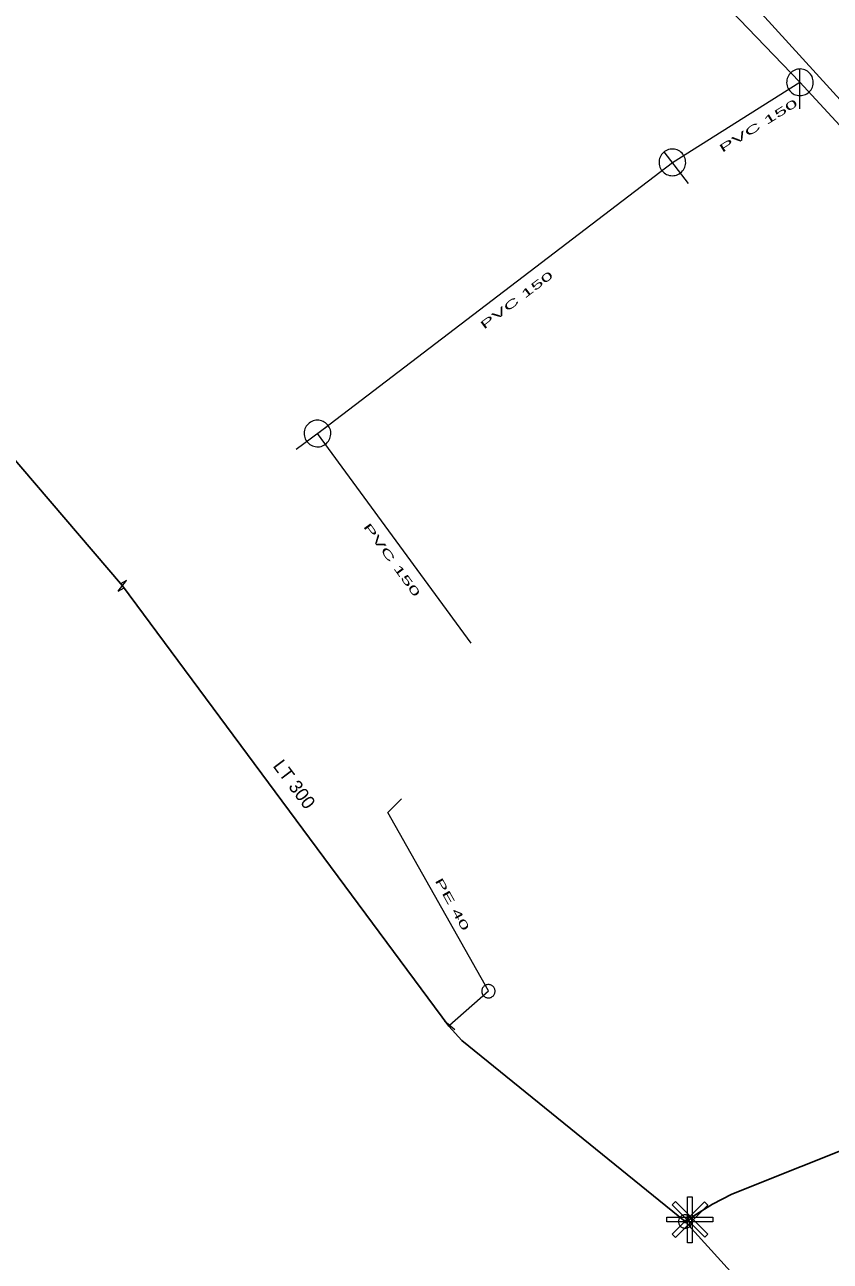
# Model space of a CAD drawing. Extents: x -809028 to -807737, y -990545 to -989489.
# Drawn here: x -808180.8 to -808120.4, y -989913.5 to -989820.9 of the extents above; entities that cross this region are included whole.
import ezdxf

# ---------------------------------------------------------------- set-up
doc = ezdxf.new("R2010")
doc.units = 0
doc.header["$LTSCALE"] = 0.32
for name, color, linetype, lineweight in [('1', 7, 'Continuous', 13), ('11', 7, 'Continuous', 13), ('12', 7, 'Continuous', 13), ('13', 7, 'Continuous', 13), ('14', 7, 'Continuous', 25), ('17', 7, 'Continuous', 25), ('22', 7, 'Continuous', 13), ('23', 7, 'Continuous', 13), ('34', 7, 'Continuous', 13), ('47', 7, 'Continuous', 13)]:
    doc.layers.add(name, color=color, linetype=linetype, lineweight=lineweight)

msp = doc.modelspace()

# ---------------------------------------------------------------- linework, layer by layer
at = {"layer": '11'}
for p, q in [((-808132.232, -989831.172), (-808122.66, -989825.17)), ((-808158.844, -989851.493), (-808132.232, -989831.172)), ((-808147.313, -989867.199), (-808158.844, -989851.493))]:
    msp.add_line(p, q, dxfattribs=at)
at = {"layer": '12'}
for points in [[(-808129.817, -989909.073), (-808129.569, -989909.321), (-808131.998, -989911.75), (-808132.245, -989911.502)], [(-808132.236, -989909.312), (-808131.989, -989909.064), (-808129.56, -989911.493), (-808129.807, -989911.741)], [(-808131.083, -989908.709), (-808130.733, -989908.709), (-808130.733, -989912.144), (-808131.083, -989912.144)], [(-808129.199, -989910.218), (-808129.199, -989910.568), (-808132.634, -989910.568), (-808132.634, -989910.218)]]:
    msp.add_lwpolyline(points, close=True, dxfattribs=at)
at = {"layer": '13'}
msp.add_line((-808148.935, -989895.847), (-808146.025, -989893.265), dxfattribs=at)
msp.add_lwpolyline([(-808146.025, -989893.265), (-808153.563, -989879.892), (-808152.541, -989878.868)], dxfattribs=at)
at = {"layer": '14', "lineweight": 13}
for p, q in [((-808149, -989895.925), (-808148.935, -989895.847)), ((-808131.01, -989910.499), (-808131.269, -989910.559))]:
    msp.add_line(p, q, dxfattribs=at)
at = {"layer": '14'}
msp.add_lwpolyline([(-808144.42, -989802.57), (-808138.872, -989808.329), (-808122.66, -989825.17), (-808105.89, -989843.32), (-808089.359, -989861.309)], dxfattribs=at)
at = {"layer": '17'}
for points in [[(-808069.18, -989881.639), (-808073.57, -989876.91), (-808074.579, -989875.82), (-808087.02, -989862.09), (-808089.66, -989859.21), (-808103.359, -989844.32), (-808106.07, -989841.379), (-808136.809, -989807.62), (-808142.09, -989802.719), (-808145.16, -989799.77), (-808145.339, -989799.479)], [(-808173.48, -989862.91), (-808188.75, -989845.079), (-808199.14, -989833.039), (-808206.761, -989824.764)], [(-808131.269, -989910.559), (-808148.03, -989896.988), (-808149, -989895.925), (-808173.48, -989862.91)], [(-808131.01, -989910.499), (-808130.809, -989910.25), (-808129.219, -989909.25), (-808127.77, -989908.51), (-808085.8, -989891.77), (-808069.925, -989882.077), (-808069.18, -989881.639)], [(-808112.855, -989924.124), (-808123.5, -989919.131), (-808131.269, -989910.559)]]:
    msp.add_lwpolyline(points, dxfattribs=at)
at = {"layer": '22'}
for p, q in [((-808122.66, -989827.17), (-808122.659, -989824.17)), ((-808131.017, -989832.761), (-808132.838, -989830.377)), ((-808160.456, -989852.676), (-808158.038, -989850.901))]:
    msp.add_line(p, q, dxfattribs=at)
for points in [[(-808121.66, -989825.17), (-808121.665, -989825.061), (-808121.683, -989824.953), (-808121.713, -989824.847), (-808121.753, -989824.746), (-808121.805, -989824.649), (-808121.867, -989824.559), (-808121.939, -989824.476), (-808122.019, -989824.402), (-808122.107, -989824.336), (-808122.201, -989824.281), (-808122.301, -989824.236), (-808122.406, -989824.203), (-808122.513, -989824.181), (-808122.622, -989824.171), (-808122.732, -989824.173), (-808122.84, -989824.187), (-808122.947, -989824.212), (-808123.05, -989824.249), (-808123.148, -989824.298), (-808123.24, -989824.356), (-808123.326, -989824.425), (-808123.403, -989824.502), (-808123.472, -989824.588), (-808123.531, -989824.68), (-808123.579, -989824.778), (-808123.616, -989824.881), (-808123.642, -989824.988), (-808123.656, -989825.096), (-808123.659, -989825.206), (-808123.649, -989825.315), (-808123.628, -989825.422), (-808123.594, -989825.526), (-808123.55, -989825.626), (-808123.495, -989825.721), (-808123.429, -989825.809), (-808123.355, -989825.889), (-808123.272, -989825.961), (-808123.182, -989826.023), (-808123.086, -989826.075), (-808122.984, -989826.116), (-808122.879, -989826.146), (-808122.771, -989826.164), (-808122.661, -989826.17), (-808122.552, -989826.164), (-808122.444, -989826.146), (-808122.339, -989826.117), (-808122.237, -989826.076), (-808122.14, -989826.024), (-808122.05, -989825.962), (-808121.967, -989825.891), (-808121.892, -989825.811), (-808121.827, -989825.723), (-808121.771, -989825.629), (-808121.727, -989825.529), (-808121.693, -989825.425), (-808121.671, -989825.317), (-808121.661, -989825.208)], [(-808131.436, -989830.565), (-808131.507, -989830.482), (-808131.587, -989830.407), (-808131.675, -989830.341), (-808131.768, -989830.285), (-808131.869, -989830.24), (-808131.973, -989830.206), (-808132.08, -989830.183), (-808132.189, -989830.173), (-808132.299, -989830.174), (-808132.407, -989830.187), (-808132.513, -989830.212), (-808132.617, -989830.25), (-808132.715, -989830.297), (-808132.808, -989830.355), (-808132.894, -989830.424), (-808132.972, -989830.5), (-808133.041, -989830.585), (-808133.101, -989830.677), (-808133.149, -989830.776), (-808133.187, -989830.878), (-808133.213, -989830.985), (-808133.228, -989831.093), (-808133.231, -989831.203), (-808133.222, -989831.312), (-808133.2, -989831.419), (-808133.167, -989831.523), (-808133.123, -989831.624), (-808133.069, -989831.718), (-808133.003, -989831.807), (-808132.929, -989831.887), (-808132.848, -989831.96), (-808132.757, -989832.022), (-808132.662, -989832.074), (-808132.56, -989832.117), (-808132.455, -989832.146), (-808132.347, -989832.165), (-808132.238, -989832.172), (-808132.128, -989832.167), (-808132.021, -989832.15), (-808131.915, -989832.12), (-808131.813, -989832.081), (-808131.716, -989832.029), (-808131.625, -989831.967), (-808131.542, -989831.896), (-808131.467, -989831.817), (-808131.401, -989831.73), (-808131.345, -989831.635), (-808131.3, -989831.535), (-808131.266, -989831.431), (-808131.243, -989831.324), (-808131.232, -989831.215), (-808131.234, -989831.106), (-808131.246, -989830.997), (-808131.272, -989830.891), (-808131.308, -989830.788), (-808131.356, -989830.689), (-808131.414, -989830.596)], [(-808158.252, -989852.299), (-808158.168, -989852.23), (-808158.091, -989852.151), (-808158.024, -989852.064), (-808157.966, -989851.972), (-808157.919, -989851.873), (-808157.883, -989851.77), (-808157.858, -989851.662), (-808157.846, -989851.554), (-808157.845, -989851.444), (-808157.856, -989851.336), (-808157.879, -989851.229), (-808157.915, -989851.124), (-808157.96, -989851.025), (-808158.017, -989850.931), (-808158.083, -989850.844), (-808158.159, -989850.765), (-808158.242, -989850.694), (-808158.333, -989850.633), (-808158.43, -989850.583), (-808158.532, -989850.543), (-808158.638, -989850.514), (-808158.746, -989850.498), (-808158.856, -989850.493), (-808158.965, -989850.5), (-808159.072, -989850.519), (-808159.177, -989850.55), (-808159.279, -989850.593), (-808159.374, -989850.645), (-808159.464, -989850.709), (-808159.546, -989850.781), (-808159.62, -989850.862), (-808159.684, -989850.951), (-808159.738, -989851.045), (-808159.782, -989851.146), (-808159.814, -989851.251), (-808159.835, -989851.358), (-808159.844, -989851.468), (-808159.84, -989851.577), (-808159.826, -989851.685), (-808159.798, -989851.792), (-808159.76, -989851.894), (-808159.711, -989851.992), (-808159.651, -989852.084), (-808159.581, -989852.168), (-808159.503, -989852.245), (-808159.417, -989852.312), (-808159.324, -989852.37), (-808159.225, -989852.417), (-808159.121, -989852.453), (-808159.015, -989852.478), (-808158.906, -989852.491), (-808158.797, -989852.492), (-808158.688, -989852.481), (-808158.581, -989852.457), (-808158.477, -989852.423), (-808158.377, -989852.377), (-808158.283, -989852.321)]]:
    msp.add_lwpolyline(points, close=True, dxfattribs=at)
at = {"layer": '23'}
for points in [[(-808145.656, -989892.961), (-808145.694, -989892.923), (-808145.735, -989892.89), (-808145.778, -989892.864), (-808145.825, -989892.84), (-808145.874, -989892.821), (-808145.925, -989892.808), (-808145.977, -989892.8), (-808146.028, -989892.798), (-808146.081, -989892.8), (-808146.132, -989892.809), (-808146.183, -989892.822), (-808146.233, -989892.842), (-808146.279, -989892.865), (-808146.321, -989892.894), (-808146.362, -989892.926), (-808146.4, -989892.965), (-808146.432, -989893.004), (-808146.461, -989893.05), (-808146.484, -989893.094), (-808146.504, -989893.143), (-808146.516, -989893.196), (-808146.524, -989893.247), (-808146.526, -989893.3), (-808146.525, -989893.352), (-808146.516, -989893.403), (-808146.501, -989893.454), (-808146.482, -989893.502), (-808146.458, -989893.548), (-808146.429, -989893.592), (-808146.397, -989893.633), (-808146.36, -989893.67), (-808146.319, -989893.703), (-808146.274, -989893.732), (-808146.228, -989893.755), (-808146.18, -989893.772), (-808146.129, -989893.786), (-808146.077, -989893.794), (-808146.024, -989893.797), (-808145.972, -989893.794)], [(-808146.461, -989893.05), (-808146.484, -989893.094), (-808146.504, -989893.143), (-808146.516, -989893.196), (-808146.524, -989893.247), (-808146.526, -989893.3), (-808146.525, -989893.352), (-808146.516, -989893.403), (-808146.501, -989893.454), (-808146.482, -989893.502), (-808146.458, -989893.548), (-808146.429, -989893.592), (-808146.397, -989893.633), (-808146.36, -989893.67), (-808146.319, -989893.703), (-808146.274, -989893.732), (-808146.228, -989893.755), (-808146.18, -989893.772), (-808146.129, -989893.786), (-808146.077, -989893.794), (-808146.024, -989893.797), (-808145.972, -989893.794), (-808145.921, -989893.786), (-808145.87, -989893.771), (-808145.822, -989893.754), (-808145.775, -989893.728), (-808145.732, -989893.7), (-808145.691, -989893.667), (-808145.655, -989893.63), (-808145.621, -989893.589), (-808145.593, -989893.545), (-808145.57, -989893.498), (-808145.551, -989893.449), (-808145.537, -989893.4), (-808145.53, -989893.347), (-808145.527, -989893.295), (-808145.53, -989893.243), (-808145.538, -989893.19), (-808145.552, -989893.14), (-808145.571, -989893.091)], [(-808145.972, -989893.794), (-808145.921, -989893.786), (-808145.87, -989893.771), (-808145.822, -989893.754), (-808145.775, -989893.728), (-808145.732, -989893.7), (-808145.691, -989893.667), (-808145.655, -989893.63), (-808145.621, -989893.589), (-808145.593, -989893.545), (-808145.57, -989893.498), (-808145.551, -989893.449), (-808145.537, -989893.4), (-808145.53, -989893.347), (-808145.527, -989893.295), (-808145.53, -989893.243), (-808145.538, -989893.19), (-808145.552, -989893.14), (-808145.571, -989893.091), (-808145.596, -989893.045), (-808145.624, -989893.002), (-808145.656, -989892.961), (-808145.694, -989892.923), (-808145.735, -989892.89), (-808145.778, -989892.864), (-808145.825, -989892.84), (-808145.874, -989892.821), (-808145.925, -989892.808), (-808145.977, -989892.8), (-808146.028, -989892.798), (-808146.081, -989892.8), (-808146.132, -989892.809), (-808146.183, -989892.822), (-808146.233, -989892.842), (-808146.279, -989892.865), (-808146.321, -989892.894), (-808146.362, -989892.926), (-808146.4, -989892.965), (-808146.432, -989893.004), (-808146.461, -989893.05)], [(-808145.571, -989893.091), (-808145.596, -989893.045), (-808145.624, -989893.002), (-808145.656, -989892.961)]]:
    msp.add_lwpolyline(points, dxfattribs=at)
at = {"layer": '34'}
for p, q in [((-808149.319, -989895.527), (-808148.55, -989896.166)), ((-808131.122, -989910.011), (-808130.898, -989910.986))]:
    msp.add_line(p, q, dxfattribs=at)
at = {"layer": '47'}
msp.add_line((-808173.796, -989863.309), (-808173.349, -989863.062), dxfattribs=at)
msp.add_lwpolyline([(-808173.796, -989863.309), (-808173.163, -989862.51), (-808173.61, -989862.757)], dxfattribs=at)
for points in [[(-808130.88, -989910.873), (-808130.85, -989910.831), (-808130.823, -989910.785), (-808130.802, -989910.738), (-808130.786, -989910.688), (-808130.775, -989910.637), (-808130.77, -989910.584), (-808130.77, -989910.532), (-808130.775, -989910.48), (-808130.786, -989910.43), (-808130.802, -989910.379), (-808130.823, -989910.331), (-808130.85, -989910.286), (-808130.88, -989910.244), (-808130.915, -989910.205), (-808130.954, -989910.17), (-808130.996, -989910.14), (-808131.042, -989910.113), (-808131.09, -989910.092), (-808131.139, -989910.076), (-808131.19, -989910.065), (-808131.243, -989910.06), (-808131.295, -989910.059), (-808131.347, -989910.065), (-808131.398, -989910.075), (-808131.448, -989910.092), (-808131.496, -989910.113), (-808131.542, -989910.139), (-808131.583, -989910.17), (-808131.622, -989910.205), (-808131.657, -989910.244), (-808131.687, -989910.286), (-808131.714, -989910.332), (-808131.736, -989910.379), (-808131.751, -989910.429), (-808131.762, -989910.48), (-808131.768, -989910.532), (-808131.768, -989910.585), (-808131.763, -989910.637), (-808131.752, -989910.688), (-808131.735, -989910.738), (-808131.714, -989910.786), (-808131.689, -989910.831), (-808131.657, -989910.873), (-808131.622, -989910.912), (-808131.583, -989910.947), (-808131.541, -989910.977), (-808131.495, -989911.004), (-808131.448, -989911.025), (-808131.398, -989911.041), (-808131.347, -989911.052), (-808131.295, -989911.058), (-808131.243, -989911.058), (-808131.191, -989911.052), (-808131.14, -989911.041), (-808131.089, -989911.025), (-808131.041, -989911.004), (-808130.997, -989910.978), (-808130.954, -989910.947), (-808130.915, -989910.912)], [(-808131.205, -989910.61), (-808131.199, -989910.603), (-808131.196, -989910.596), (-808131.192, -989910.588), (-808131.189, -989910.58), (-808131.188, -989910.571), (-808131.187, -989910.563), (-808131.186, -989910.554), (-808131.187, -989910.546), (-808131.19, -989910.537), (-808131.192, -989910.529), (-808131.196, -989910.521), (-808131.2, -989910.514), (-808131.205, -989910.507), (-808131.21, -989910.5), (-808131.217, -989910.495), (-808131.224, -989910.489), (-808131.231, -989910.486), (-808131.239, -989910.482), (-808131.247, -989910.479), (-808131.256, -989910.478), (-808131.264, -989910.477), (-808131.273, -989910.476), (-808131.281, -989910.477), (-808131.29, -989910.479), (-808131.298, -989910.482), (-808131.306, -989910.486), (-808131.313, -989910.49), (-808131.32, -989910.495), (-808131.327, -989910.5), (-808131.332, -989910.507), (-808131.338, -989910.514), (-808131.341, -989910.521), (-808131.345, -989910.529), (-808131.348, -989910.537), (-808131.349, -989910.546), (-808131.351, -989910.554), (-808131.351, -989910.563), (-808131.35, -989910.571), (-808131.348, -989910.58), (-808131.345, -989910.588), (-808131.341, -989910.596), (-808131.337, -989910.603), (-808131.332, -989910.61), (-808131.327, -989910.617), (-808131.32, -989910.622), (-808131.313, -989910.628), (-808131.306, -989910.631), (-808131.298, -989910.635), (-808131.29, -989910.638), (-808131.281, -989910.639), (-808131.273, -989910.641), (-808131.264, -989910.641), (-808131.256, -989910.64), (-808131.247, -989910.637), (-808131.239, -989910.635), (-808131.231, -989910.631), (-808131.224, -989910.627), (-808131.217, -989910.622), (-808131.21, -989910.617)]]:
    msp.add_lwpolyline(points, close=True, dxfattribs=at)

# ---------------------------------------------------------------- texts
at = {"layer": '1'}
for s, rotation, width, p in [('PVC 150 ', 32, 2.1, (-808128.485, -989830.464)), ('PVC 150 ', 37, 2.05, (-808146.362, -989843.712)), ('PVC 150 ', 306, 2.05, (-808155.442, -989858.476)), ('PE 40 ', 299, 2, (-808150.059, -989885.005))]:
    msp.add_text(s, height=0.6, rotation=rotation, dxfattribs=dict(at, width=width)).set_placement(p)
msp.add_text('LT 300', height=1, rotation=307, dxfattribs=at).set_placement((-808162.234, -989876.42))

doc.saveas('drawing.dxf')
